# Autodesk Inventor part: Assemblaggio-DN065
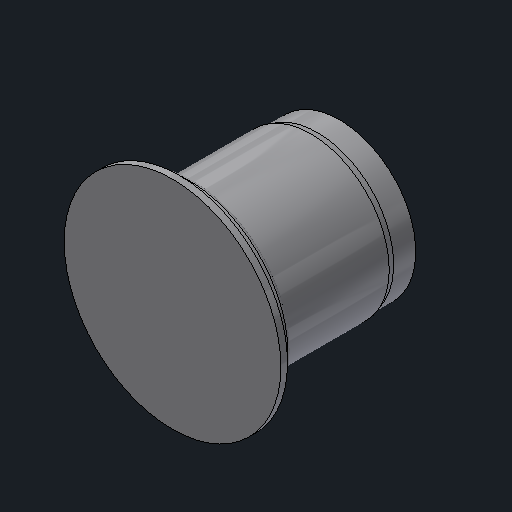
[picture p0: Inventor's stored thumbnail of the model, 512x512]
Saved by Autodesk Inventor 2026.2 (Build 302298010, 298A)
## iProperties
Created: 2026-03
Part Number: Assemblaggio-DN065
Material: Generico
Document SubType Name: Modeling
Designer: marz-m
Density: 1 g/cm^3
Appearance: Default
Author: marz-m
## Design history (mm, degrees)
feature "Solido1"
node "Solido2"
